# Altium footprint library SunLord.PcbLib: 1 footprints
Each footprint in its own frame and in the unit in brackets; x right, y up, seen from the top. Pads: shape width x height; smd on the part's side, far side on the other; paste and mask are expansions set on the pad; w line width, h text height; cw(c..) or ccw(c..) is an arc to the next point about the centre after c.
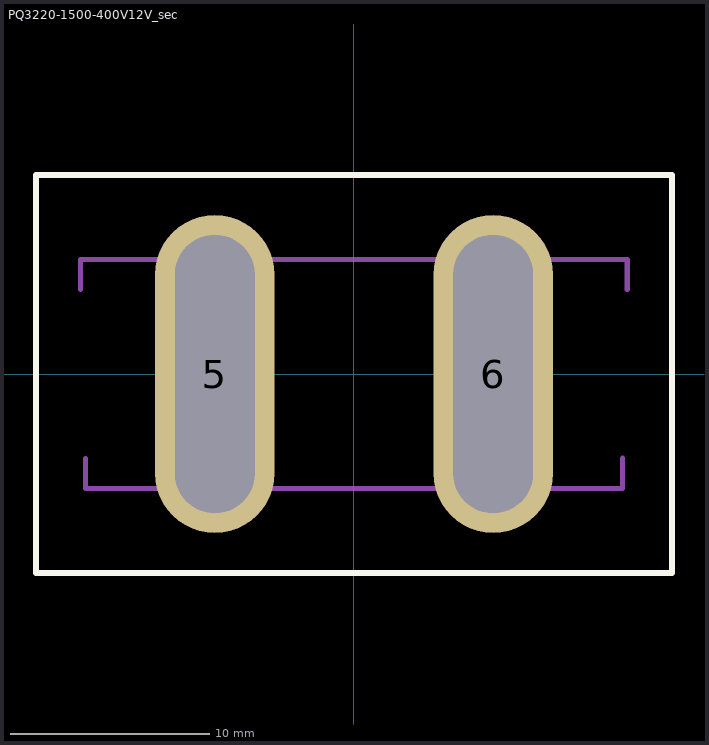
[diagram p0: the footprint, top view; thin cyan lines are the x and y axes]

## PQ3220-1500-400V12V_sec [mm] "1500W Transformer from 400V to 12V with PQ3220 Core"
height 30
pads (2):
  oval 6x16 / inner oval 3x4 / far side oval 4x6 hole 4 slot 14 at 90 deg: 5(-7,0)
  oval 6x16 / inner oval 2.5x3.5 / far side oval 4x6 hole 4 slot 14 at 90 deg: 6(7,0)
Top Overlay:
  lines w0.3: 16,-10 -16,-10 -16,10 16,10 ; 16,-9.993 16,9.958
M2 Board Dimensions:
  lines w0.254: -13.75,5.75 13.75,5.75 ; -13.743,4.246 -13.743,5.746 ; -13.513,-5.745 -13.513,-4.245 ; -13.5,-5.75 13.5,-5.75 ; -9.35,-5.75 -9.35,5.75 ; 9.35,-5.75 9.35,5.75 ; 13.493,-5.734 13.493,-4.234 ; 13.739,4.244 13.739,5.744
